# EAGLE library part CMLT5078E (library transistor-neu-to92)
DUAL COMPLEMENTARY: L78 TRANSISTORS ENHANCED SPECIFICATION PICOmini(TM) SURFACE MOUNT Source: CMLT5078%20SERIES.pdf
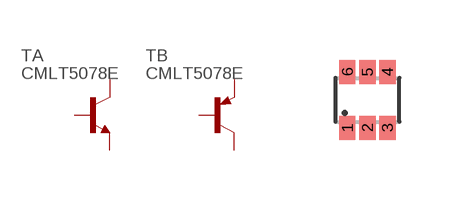
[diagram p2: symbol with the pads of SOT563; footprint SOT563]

Designator prefix T; gates A=NPN B=PNP

## CMLT5078E  [SOT563]
1  A:E  pas
2  A:B  pas
3  B:C  pas
4  B:E  pas
5  B:B  pas
6  A:C  pas

## Footprint SOT563 (pad centres in mm)
SOT-563 Source: www.centralsemi.com ..SOT-563PD.pdf
smd 0.4 x 0.6: 1 -0.5,-0.7; 2 0,-0.7; 3 0.5,-0.7; 4 0.5,0.7; 5 0,0.7; 6 -0.5,0.7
